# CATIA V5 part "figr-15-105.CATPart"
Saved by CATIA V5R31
Part number: Part1
Bounding box of the stored display mesh (mm): x -66.07 to 66.07, y -35.456 to 35.456, z -8 to 1
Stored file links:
  D:\PROJECTS\Project 2021\US EDITION\CATIA V5 6R 2021\Resources\Part Files\c15_catia_v5_6r2021_prt\figr-15-105.CATPart
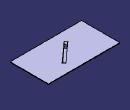
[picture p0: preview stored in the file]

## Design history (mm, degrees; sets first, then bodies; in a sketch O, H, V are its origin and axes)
SheetMetalParameters1: Thickness 1, BendRadius 5, KFactor 0.5 {= log(min(100,max(20*SheetMetalParameters1.BendRadius,SheetMetalParameters1.Thickness)/SheetMetalParameters1.Thickness))/log(100)/2}, ReliefRadialLength 1, ReliefAxialLength 2, MinimumBendRadius 0
Body1 (main body)
  Sketch1 on xy-plane, origin (0, 0, 0), H (1, 0, 0), V (0, 1, 0)
    line L1 (66.07, 35.4565) -> (66.07, -35.4565)
    line L2 (66.07, -35.4565) -> (-66.07, -35.4565)
    line L3 (-66.07, -35.4565) -> (-66.07, 35.4565)
    line L4 (-66.07, 35.4565) -> (66.07, 35.4565)
    vertical: L1 V, L3 V
    horizontal: L2 H, L4 H
    equidistance: L1 L3 O, L2 L4 O
  Wall1: Thickness 1, Profile Sketch1
  Sketch2 on face of Wall1, origin (0, 0, 1), H (1, 0, 0), V (0, 1, 0)
    point P1 (0, 0)
    coincidence: P1 O
  Sketch3 on face of Wall1, origin (0, 0, 1), H (1, 0, 0), V (0, 1, 0)
    point P1 (0, 0)
    reference projected point E1 (0, 0) from Sketch2.P1
    coincidence: E1 P1
  d_Stamp1: Stamp_FilletRadius 2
